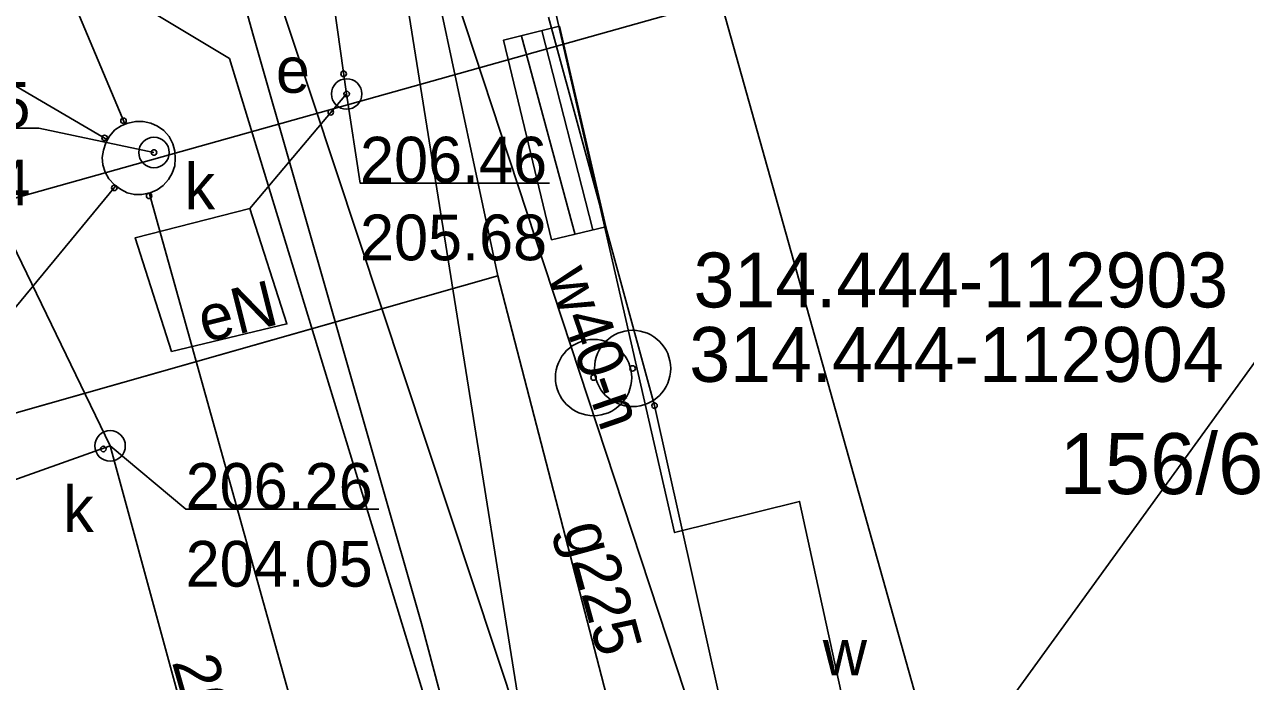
# Model space of a CAD drawing. Extents: x 6512606 to 6513347, y 6022524 to 6022728.
# Drawn here: x 6512852.29 to 6512872.32, y 6022610.86 to 6022621.63 of the extents above; entities that cross this region are included whole.
import ezdxf

# ---------------------------------------------------------------- set-up
doc = ezdxf.new("R2010")
doc.units = 0
for name, color, linetype in [('121-Punkt osnowy szczegółowej', 7, 'Continuous'), ('121-Punkt osnowy szczegółowej-Atr103', 7, 'Continuous'), ('203-punkt graniczny', 7, 'Continuous'), ('211-numer działki ewidencyjnej', 7, 'Continuous'), ('217-kontur klasyfikacyjny', 7, 'Continuous'), ('218-kontur użytku gruntowego', 7, 'Continuous'), ('219-działka ewidencyjna', 7, 'Continuous'), ('352-schody', 7, 'Continuous'), ('4', 7, 'Continuous'), ('budynek projektowany (powierzchnia)', 7, 'Continuous'), ('Default', 7, 'Continuous'), ('inna obudowa przewodu - sieć gazowa (linia)', 7, 'Continuous'), ('komora podziemna - przewód kanalizacyjny (powierzchnia)', 7, 'Continuous'), ('krawężnik (linia)', 7, 'Continuous'), ('maxp_opisy', 7, 'Continuous'), ('Obszar opracowania', 7, 'Continuous'), ('przewód elektroenergetyczny (linia)', 7, 'Continuous'), ('przewód elektroenergetyczny (linia)-Atr1', 7, 'Continuous'), ('przewód elektroenergetyczny niskiego napięcia (linia)', 7, 'Continuous'), ('przewód gazowy (linia)', 7, 'Continuous'), ('przewód gazowy (linia)-Atr1', 7, 'Continuous'), ('przewód kanalizacyjny (linia)', 7, 'Continuous'), ('przewód wodociągowy (linia)', 7, 'Continuous'), ('przewód wodociągowy (linia)-Atr1', 7, 'Continuous'), ('punkt o określonej wysokości (sieć elektroenergetyczna)', 7, 'Continuous'), ('punkt o określonej wysokości (sieć elektroenergetyczna)-Atr2', 7, 'Continuous'), ('punkt o określonej wysokości (sieć elektroenergetyczna)-Atr3', 7, 'Continuous'), ('punkt o określonej wysokości (sieć kanalizacyjna)', 7, 'Continuous'), ('punkt o określonej wysokości (sieć kanalizacyjna)-Atr2', 7, 'Continuous'), ('punkt o określonej wysokości (sieć kanalizacyjna)-Atr3', 7, 'Continuous'), ('punkt wysokościowy sztuczny-Atr2', 7, 'Continuous'), ('właz okrągły - siec elektroenergetyczna (punkt)', 7, 'Continuous'), ('właz okrągły - siec elektroenergetyczna (punkt)-Atr17', 7, 'Continuous'), ('właz okrągły - siec kanalizacyjna (punkt)', 7, 'Continuous'), ('właz okrągły - siec kanalizacyjna (punkt)-Atr17', 7, 'Continuous'), ('właz okrągły - siec wodociągowa (punkt)-Atr17', 7, 'Continuous')]:
    doc.layers.add(name, color=color, linetype=linetype)

# ---------------------------------------------------------------- blocks, each defined once
blk = doc.blocks.new('203')
at = {"layer": 'Default'}
blk.add_circle((0, 0), 0.45, dxfattribs=at)
blk = doc.blocks.new('PW01')
at = {"layer": 'Default'}
blk.add_circle((0, 0), 0.45, dxfattribs=at)
blk = doc.blocks.new('US22')
at = {"layer": 'Default'}
blk.add_circle((0, 0), 2.5, dxfattribs=at)
blk = doc.blocks.new('121')
at = {"layer": 'Default'}
for radius in [6.25, 0.45]:
    blk.add_circle((0, 0), radius, dxfattribs=at)

msp = doc.modelspace()

# ---------------------------------------------------------------- linework, layer by layer
at = {"layer": '217-kontur klasyfikacyjny'}
for points in [[(6512860.89, 6022621.75), (6512862.63, 6022615.38)], [(6512862.63, 6022615.38), (6512866.69, 6022597.16)]]:
    msp.add_lwpolyline(points, dxfattribs=at)
at = {"layer": '218-kontur użytku gruntowego'}
for points in [[(6512860.89, 6022621.75), (6512862.63, 6022615.38)], [(6512862.63, 6022615.38), (6512860.89, 6022621.75)], [(6512862.63, 6022615.38), (6512866.69, 6022597.16)], [(6512866.69, 6022597.16), (6512862.63, 6022615.38)]]:
    msp.add_lwpolyline(points, dxfattribs=at)
at = {"layer": '219-działka ewidencyjna'}
for points in [[(6512862.63, 6022615.38), (6512860.89, 6022621.75)], [(6512866.69, 6022597.16), (6512862.63, 6022615.38)]]:
    msp.add_lwpolyline(points, dxfattribs=at)
at = {"layer": '352-schody'}
msp.add_lwpolyline([(6512860.94, 6022618.1), (6512861.83, 6022618.31), (6512861.07, 6022621.6), (6512860.15, 6022621.37)], close=True, dxfattribs=at)
msp.add_lwpolyline([(6512860.94, 6022618.1), (6512861.83, 6022618.31), (6512861.07, 6022621.6), (6512860.15, 6022621.37)], close=True, dxfattribs=at)
for points in [[(6512860.45, 6022621.44), (6512861.33, 6022618.18)], [(6512860.45, 6022621.44), (6512861.33, 6022618.18)], [(6512861.62, 6022618.26), (6512860.78, 6022621.53)], [(6512861.62, 6022618.26), (6512860.78, 6022621.53)]]:
    msp.add_lwpolyline(points, dxfattribs=at)
at = {"layer": '4'}
for points in [[(6512862.63, 6022615.38), (6512860.89, 6022621.75)], [(6512866.69, 6022597.16), (6512862.63, 6022615.38)]]:
    msp.add_lwpolyline(points, dxfattribs=at)
at = {"layer": 'budynek projektowany (powierzchnia)'}
msp.add_lwpolyline([(6512876.905, 6022604.629), (6512866.3, 6022602.19), (6512866.5, 6022601.27), (6512865.79, 6022601.1), (6512863.94, 6022609.18), (6512865.92, 6022609.63), (6512865.01, 6022613.81), (6512862.96, 6022613.3), (6512860.72, 6022623.09)], dxfattribs=at)
at = {"layer": 'inna obudowa przewodu - sieć gazowa (linia)'}
msp.add_lwpolyline([(6512857.81, 6022616.87), (6512847.79, 6022614.02)], dxfattribs=at)
at = {"layer": 'komora podziemna - przewód kanalizacyjny (powierzchnia)'}
msp.add_lwpolyline([(6512854.77, 6022619.43), (6512854.76, 6022619.31), (6512854.72, 6022619.19), (6512854.66, 6022619.09), (6512854.57, 6022618.99), (6512854.47, 6022618.92), (6512854.36, 6022618.87), (6512854.22, 6022618.84), (6512854.1, 6022618.84), (6512853.98, 6022618.87), (6512853.87, 6022618.93), (6512853.77, 6022619), (6512853.68, 6022619.1), (6512853.62, 6022619.21), (6512853.58, 6022619.33), (6512853.57, 6022619.45), (6512853.59, 6022619.57), (6512853.63, 6022619.69), (6512853.69, 6022619.8), (6512853.78, 6022619.9), (6512853.88, 6022619.97), (6512853.99, 6022620.01), (6512854.12, 6022620.04), (6512854.24, 6022620.04), (6512854.37, 6022620.01), (6512854.48, 6022619.96), (6512854.58, 6022619.89), (6512854.67, 6022619.79), (6512854.73, 6022619.67), (6512854.76, 6022619.55)], close=True, dxfattribs=at)
at = {"layer": 'krawężnik (linia)'}
msp.add_lwpolyline([(6512859.76, 6022608.23), (6512858.81, 6022611.81), (6512856.05, 6022621.44), (6512855.08, 6022624.94), (6512854.44, 6022627.77)], dxfattribs=at)
at = {"layer": 'maxp_opisy'}
msp.add_lwpolyline([(6512856.121, 6022593.53), (6512879.345, 6022625.572), (6512868.61, 6022653.292)], dxfattribs=at)
at = {"layer": 'Obszar opracowania'}
msp.add_lwpolyline([(6512710.98, 6022693.84), (6512748.35, 6022694.16), (6512798.11, 6022695.25), (6512807.47, 6022695.46), (6512809.66, 6022606.87), (6512863.71, 6022622.03), (6512875.13, 6022581.36), (6512755.22, 6022535.25), (6512691.61, 6022568.03), (6512709.16, 6022605.16)], close=True, dxfattribs=at)
at = {"layer": 'przewód elektroenergetyczny (linia)'}
for points in [[(6512856.39, 6022640.68), (6512854.91, 6022639.46), (6512857.58, 6022620.49)], [(6512857.58, 6022620.49), (6512855.99, 6022618.61), (6512856.6, 6022616.72), (6512854.71, 6022616.27), (6512854.11, 6022618.13), (6512855.99, 6022618.61)]]:
    msp.add_lwpolyline(points, dxfattribs=at)
at = {"layer": 'przewód elektroenergetyczny niskiego napięcia (linia)'}
msp.add_lwpolyline([(6512861.56, 6022603.29), (6512856.13, 6022637.29)], dxfattribs=at)
at = {"layer": 'przewód gazowy (linia)'}
for points in [[(6512871.862, 6022571.535), (6512870.29, 6022578.43), (6512869.58, 6022581.52), (6512865.64, 6022595.96), (6512860.06, 6022617.51), (6512858.39, 6022625.33), (6512855.49, 6022634.19), (6512854.83, 6022641.62)], [(6512860.06, 6022617.51), (6512847.79, 6022614.02)]]:
    msp.add_lwpolyline(points, dxfattribs=at)
at = {"layer": 'przewód kanalizacyjny (linia)'}
for points in [[(6512853.94, 6022620), (6512836.1, 6022662.34)], [(6512853.7, 6022614.72), (6512848.55, 6022625.36), (6512840.81, 6022640.51)], [(6512848.69, 6022622.65), (6512853.66, 6022619.74)], [(6512853.79, 6022618.98), (6512850.12, 6022614.54), (6512848.32, 6022618.08)], [(6512860.32, 6022597.43), (6512854.34, 6022618.87)], [(6512832.23, 6022607.08), (6512853.7, 6022614.72)], [(6512861.16, 6022586.16), (6512858.32, 6022597.78), (6512853.7, 6022614.72)]]:
    msp.add_lwpolyline(points, dxfattribs=at)
at = {"layer": 'przewód wodociągowy (linia)'}
for points in [[(6512861.84, 6022602.88), (6512860.4, 6022610.22), (6512855.52, 6022624.92), (6512854.13, 6022628.72), (6512853.02, 6022630.73), (6512851.7, 6022633.1), (6512848.7, 6022639.72)], [(6512855.66, 6022621.07), (6512846.88, 6022626.34), (6512844.27, 6022630.32), (6512839.99, 6022636.93), (6512839.52, 6022638)], [(6512863.27, 6022610.25), (6512857.52, 6022627.72)], [(6512859.28, 6022609.22), (6512855.66, 6022621.07)]]:
    msp.add_lwpolyline(points, dxfattribs=at)
at = {"layer": 'punkt o określonej wysokości (sieć elektroenergetyczna)-Atr2'}
msp.add_lwpolyline([(6512857.58, 6022620.49), (6512857.8, 6022619.03), (6512860.909, 6022619.03)], dxfattribs=at)
at = {"layer": 'punkt o określonej wysokości (sieć kanalizacyjna)-Atr2'}
for points in [[(6512854.42, 6022619.53), (6512852.53, 6022619.93), (6512849.326, 6022619.93)], [(6512853.7, 6022614.72), (6512854.94, 6022613.68), (6512858.107, 6022613.68)]]:
    msp.add_lwpolyline(points, dxfattribs=at)

# ---------------------------------------------------------------- block references
at = {"layer": '121-Punkt osnowy szczegółowej', "xscale": 0.1, "yscale": 0.10000000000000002}
for p in [(6512862.27, 6022615.99), (6512861.63, 6022615.84)]:
    msp.add_blockref('121', p, dxfattribs=at)
at = {"layer": '203-punkt graniczny', "xscale": 0.1, "yscale": 0.10000000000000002}
msp.add_blockref('203', (6512862.63, 6022615.38), dxfattribs=at)
at = {"layer": 'punkt o określonej wysokości (sieć elektroenergetyczna)'}
for p, xscale, yscale, rotation in [((6512857.53, 6022620.82), 0.09999999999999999, 0.1, -81.201), ((6512857.58, 6022620.49), 0.09999999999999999, 0.1, 98.805), ((6512857.32, 6022620.19), 0.1, 0.09999999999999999, 50.759)]:
    msp.add_blockref('PW01', p, dxfattribs=dict(at, xscale=xscale, yscale=yscale, rotation=rotation))
at = {"layer": 'punkt o określonej wysokości (sieć kanalizacyjna)'}
for p, xscale, yscale, rotation in [((6512853.92, 6022620.05), 0.1, 0.10000000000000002, -66.353), ((6512853.61, 6022619.77), 0.10000000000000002, 0.1, -29.547), ((6512853.77, 6022618.95), 0.1, 0.10000000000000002, 51.278000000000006), ((6512854.34, 6022618.82), 0.1, 0.09999999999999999, -73.603)]:
    msp.add_blockref('PW01', p, dxfattribs=dict(at, xscale=xscale, yscale=yscale, rotation=rotation))
at = {"layer": 'punkt o określonej wysokości (sieć kanalizacyjna)', "xscale": 0.1, "yscale": 0.10000000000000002}
for p in [(6512854.42, 6022619.53), (6512853.59, 6022614.67)]:
    msp.add_blockref('PW01', p, dxfattribs=at)
at = {"layer": 'właz okrągły - siec elektroenergetyczna (punkt)', "xscale": 0.09999999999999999, "yscale": 0.1, "rotation": 98.805}
msp.add_blockref('US22', (6512857.58, 6022620.49), dxfattribs=at)
at = {"layer": 'właz okrągły - siec kanalizacyjna (punkt)', "xscale": 0.1, "yscale": 0.10000000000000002}
for p in [(6512854.42, 6022619.53), (6512853.7, 6022614.72)]:
    msp.add_blockref('US22', p, dxfattribs=at)

# ---------------------------------------------------------------- texts
at = {"layer": '121-Punkt osnowy szczegółowej-Atr103'}
for s, p in [('314.444-112903', (6512863.27, 6022616.99)), ('314.444-112904', (6512863.2, 6022615.77))]:
    msp.add_text(s, height=0.9, dxfattribs=at).set_placement(p)
at = {"layer": '211-numer działki ewidencyjnej'}
msp.add_text('156/6', height=1, dxfattribs=at).set_placement((6512869.27, 6022613.93))
at = {"layer": '4'}
msp.add_text('156/6', height=1, dxfattribs=at).set_placement((6512869.27, 6022613.93))
at = {"layer": 'przewód elektroenergetyczny (linia)-Atr1'}
msp.add_text('eN', height=0.75, rotation=14.036, dxfattribs=at).set_placement((6512855.25, 6022616.41))
at = {"layer": 'przewód gazowy (linia)-Atr1'}
msp.add_text('g225', height=0.75, rotation=285.315, dxfattribs=at).set_placement((6512861.13, 6022613.38))
at = {"layer": 'przewód wodociągowy (linia)-Atr1'}
msp.add_text('w40-n', height=0.75, rotation=289.019, dxfattribs=at).set_placement((6512860.88, 6022617.51))
at = {"layer": 'punkt o określonej wysokości (sieć elektroenergetyczna)-Atr2'}
msp.add_text('206.46', height=0.75, dxfattribs=at).set_placement((6512857.8, 6022619.038))
at = {"layer": 'punkt o określonej wysokości (sieć elektroenergetyczna)-Atr3'}
msp.add_text('205.68', height=0.75, dxfattribs=at).set_placement((6512857.8, 6022617.763))
at = {"layer": 'punkt o określonej wysokości (sieć kanalizacyjna)-Atr2'}
for s, p in [('206.25', (6512849.326, 6022619.938)), ('206.26', (6512854.94, 6022613.688))]:
    msp.add_text(s, height=0.75, dxfattribs=at).set_placement(p)
at = {"layer": 'punkt o określonej wysokości (sieć kanalizacyjna)-Atr3'}
for s, p in [('204.34', (6512849.326, 6022618.662)), ('204.05', (6512854.94, 6022612.412))]:
    msp.add_text(s, height=0.75, dxfattribs=at).set_placement(p)
at = {"layer": 'punkt wysokościowy sztuczny-Atr2'}
msp.add_text('206.13', height=0.75, rotation=285.965, dxfattribs=at).set_placement((6512854.71, 6022611.18))
at = {"layer": 'właz okrągły - siec elektroenergetyczna (punkt)-Atr17'}
msp.add_text('e', height=0.75, dxfattribs=at).set_placement((6512856.42, 6022620.51))
at = {"layer": 'właz okrągły - siec kanalizacyjna (punkt)-Atr17'}
for p in [(6512854.92, 6022618.6), (6512852.93, 6022613.31)]:
    msp.add_text('k', height=0.75, dxfattribs=at).set_placement(p)
at = {"layer": 'właz okrągły - siec wodociągowa (punkt)-Atr17'}
msp.add_text('w', height=0.75, dxfattribs=at).set_placement((6512865.39, 6022610.96))

doc.saveas('drawing.dxf')
